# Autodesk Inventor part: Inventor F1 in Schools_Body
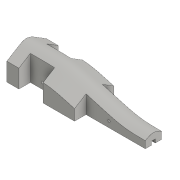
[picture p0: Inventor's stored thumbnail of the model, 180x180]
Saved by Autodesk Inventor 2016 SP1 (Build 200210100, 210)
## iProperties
Category: F1 in Schools
Company: Autodesk Inc.
Created: 2015-12
Part Number: Inventor F1 in Schools_Body
Material: Generic
Document SubType Name: Modeling
Designer: Autodesk Inc.
Density: 1 g/cm^3
Appearance: Default
Author: Autodesk Inc
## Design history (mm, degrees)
sketch "Sketch1"
  geometry: L1 (0, 0)-(-65, 0); L2 (-65, 0)-(-65, -210); L3 (-65, -210)-(0, -210); L4 (0, -210)-(0, 0)
  constraints: 8 end point, 2 parallel, 1 horizontal, 1 perpendicular
  dimensions: "d0" = 65 distance of L3.end L2.end; "d1" = 210 distance of L2.end L1.end
extrude "Extrusion1" new body sketch "Sketch1" distance "d2" = 50; taper "d3" = 0 deg
sketch "Sketch2"
  geometry: L1 (0, 0)-(65, 0) reference; L2 (65, 0)-(65, 50) reference; C1 r 9.5 at (32.5, 29)
  constraints: 1 centre point
  dimensions: "d4" = 19 diameter of C1; "d5" = 29 distance from line of L1 C1.centre; "d6" = 32.5 distance from line of L2 C1.centre
extrude "Extrusion2" cut sketch "Sketch2" distance "d7" = 50; taper "d8" = 0 deg
sketch "Sketch3"
  geometry: L1 (0, 0)-(65, 0) reference; L2 (29.5, 0)-(35.5, 0); L3 (35.5, 0)-(35.5, 6); L4 (35.5, 6)-(29.5, 6); L5 (29.5, 6)-(29.5, 0); 2 further points
  constraints: 8 end point, 2 midpoint, 2 parallel, 1 collinear, 1 horizontal, 1 perpendicular, 1 vertical alignment
  dimensions: "d11" = 6 distance of L4.end L3.end; "d12" = 6 distance of L3.end L2.end
extrude "Extrusion3" cut sketch "Sketch3" stored distance "d13" = 10; taper "d14" = 0 deg
sketch "Sketch4"
  geometry: L1 (0, 0)-(0, 50) reference; L2 (0, 0)-(210, 0) reference; L3 (210, 0)-(210, 50) reference; 2 further points
  dimensions: "d15" = 40 distance from line of point (40, 10) L1; "d16" = 10 distance from line of point (40, 10) L2; "d17" = 60 distance from line of point (150, 10) L3; "d18" = 10 distance from line of point (150, 10) L2
hole "Hole1" sketch "Sketch4" at (40, 10), (150, 10) diameter "d19" = 4; stored, may be unused: countersink angle "d23" = 90 deg, drill point angle "d25" = 118 deg; dims "d20" = 6, "d21" = 4, "d22" = 2, "d24" = 8
sketch "Sketch5"
  geometry: L1 (46, 98)-(65, 98); L2 (65, 98)-(65, 0); L3 (65, 0)-(46, 0); L4 (46, 0)-(46, 98); L5 (0, 0)-(65, 0) reference; L6 (65, 0)-(65, 210) reference; L7 (65, 190)-(46, 190); L8 (46, 190)-(46, 150); L9 (46, 150)-(65, 150); L10 (65, 150)-(65, 190); L11 (65, 210)-(0, 210) reference
  constraints: 16 end point, 4 parallel, 3 collinear, 2 horizontal, 2 perpendicular
  dimensions: "d26" = 98 distance of L3.end L1.start; "d27" = 19 distance of L2.end L3.end; "d28" = 20 distance between parallel lines of L11 L7; "d29" = 19 distance of L7.start L7.end; "d30" = 40 distance of L9.end L7.start
extrude "Extrusion4" cut sketch "Sketch5" stored distance "d31" = 10; taper "d32" = 0 deg
workplane "Work Plane1"
mirror "Mirror1"
workplane "Work Plane5"
sketch "Sketch11"
  geometry: L1 (19, 0)-(46, 0) reference; L2 (65, 210)-(0, 210) reference; 3 further points
  constraints: 1 midpoint, 1 vertical alignment
  dimensions: "d45" = 105 distance from line of point (32.5, 105) L1
feature "Form1"
split "Split1"
body "Solid1"
body "Srf1"
other parameters: "d44" = 0
